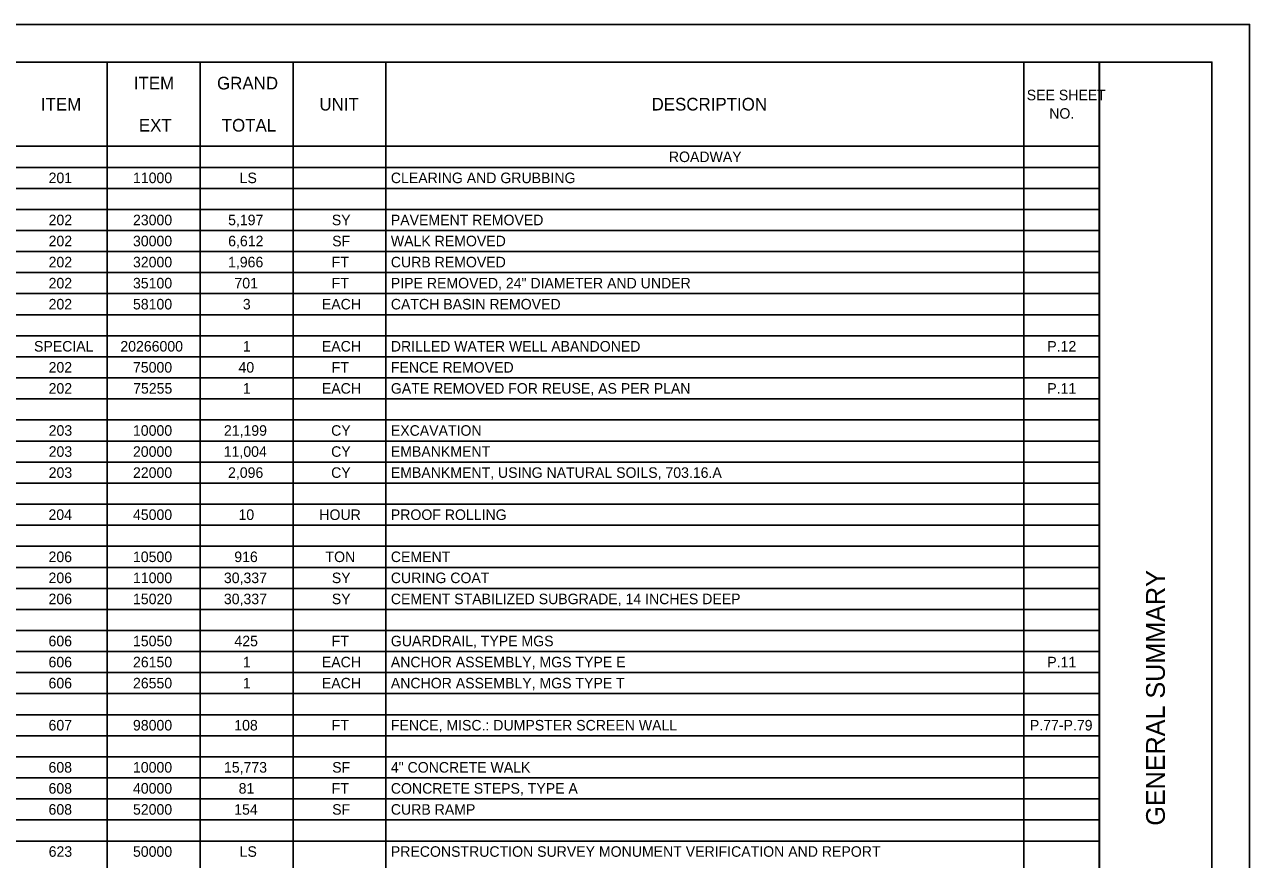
# Model space of a CAD drawing. Extents: x 0 to 34, y 0 to 22.
# Drawn here: x 17.71 to 34, y 10.89 to 22 of the extents above; entities that cross this region are included whole.
import ezdxf

# ---------------------------------------------------------------- set-up
doc = ezdxf.new("R2010")
doc.units = 0
for name, color, linetype in [('SH_Border', 7, 'Continuous'), ('SH_Cut_Line', 7, 'Continuous'), ('SH_Data', 7, 'Continuous'), ('SH_Text', 7, 'Continuous')]:
    doc.layers.add(name, color=color, linetype=linetype)

msp = doc.modelspace()

# ---------------------------------------------------------------- linework, layer by layer
at = {"layer": 'SH_Border'}
msp.add_line((32, 0.5), (32, 21.5), dxfattribs=at)
msp.add_lwpolyline([(1.5, 21.5), (33.5, 21.5), (33.5, 0.5), (1.5, 0.5)], close=True, dxfattribs=at)
at = {"layer": 'SH_Cut_Line'}
msp.add_lwpolyline([(0, 0), (34, 0), (34, 22), (0, 22)], close=True, dxfattribs=at)
at = {"layer": 'SH_Text'}
for p, q in [((1.5, 21.5), (32.004, 21.5)), ((18.811, 21.5), (18.811, 0.5)), ((20.046, 21.5), (20.046, 0.5)), ((21.281, 21.5), (21.281, 0.5)), ((22.516, 21.5), (22.516, 0.5)), ((30.999, 21.5), (30.999, 0.5)), ((32.004, 21.5), (32.004, 0.5)), ((1.5, 20.38), (32.004, 20.38)), ((1.5, 20.1), (32.004, 20.1)), ((1.5, 19.82), (32.004, 19.82)), ((1.5, 19.54), (32.004, 19.54)), ((1.5, 19.26), (32.004, 19.26)), ((1.5, 18.98), (32.004, 18.98)), ((1.5, 18.7), (32.004, 18.7)), ((1.5, 18.42), (32.004, 18.42)), ((1.5, 18.14), (32.004, 18.14)), ((1.5, 17.86), (32.004, 17.86)), ((1.5, 17.58), (32.004, 17.58)), ((1.5, 17.3), (32.004, 17.3)), ((1.5, 17.02), (32.004, 17.02)), ((1.5, 16.74), (32.004, 16.74)), ((1.5, 16.46), (32.004, 16.46)), ((1.5, 16.18), (32.004, 16.18)), ((1.5, 15.9), (32.004, 15.9)), ((1.5, 15.62), (32.004, 15.62)), ((1.5, 15.34), (32.004, 15.34)), ((1.5, 15.06), (32.004, 15.06)), ((1.5, 14.78), (32.004, 14.78)), ((1.5, 14.5), (32.004, 14.5)), ((1.5, 14.22), (32.004, 14.22)), ((1.5, 13.94), (32.004, 13.94)), ((1.5, 13.66), (32.004, 13.66)), ((1.5, 13.38), (32.004, 13.38)), ((1.5, 13.1), (32.004, 13.1)), ((1.5, 12.82), (32.004, 12.82)), ((1.5, 12.54), (32.004, 12.54)), ((1.5, 12.26), (32.004, 12.26)), ((1.5, 11.98), (32.004, 11.98)), ((1.5, 11.7), (32.004, 11.7)), ((1.5, 11.42), (32.004, 11.42)), ((1.5, 11.14), (32.004, 11.14))]:
    msp.add_line(p, q, dxfattribs=at)

# ---------------------------------------------------------------- texts
at = {"layer": 'SH_Data'}
msp.add_text('GENERAL SUMMARY', height=0.25, rotation=90, dxfattribs=at).set_placement((32.875, 11.344))
at = {"layer": 'SH_Text'}
for s, height, p in [('ITEM', 0.168, (19.164, 21.136)), ('GRAND', 0.168, (20.271, 21.136)), ('ITEM', 0.168, (17.928, 20.856)), ('UNIT', 0.168, (21.632, 20.856)), ('DESCRIPTION', 0.168, (26.049, 20.856)), ('SEE SHEET ', 0.14, (31.038, 20.992)), ('NO.', 0.14, (31.337, 20.747)), ('EXT', 0.168, (19.231, 20.576)), ('TOTAL', 0.168, (20.333, 20.576)), ('ROADWAY', 0.14, (26.279, 20.17)), ('201', 0.14, (18.031, 19.89)), ('11000', 0.14, (19.153, 19.89)), ('LS', 0.14, (20.571, 19.89)), ('CLEARING AND GRUBBING', 0.14, (22.582, 19.89)), ('202', 0.14, (18.031, 19.33)), ('23000', 0.14, (19.153, 19.33)), ('5,197', 0.14, (20.418, 19.33)), ('SY', 0.14, (21.797, 19.33)), ('PAVEMENT REMOVED', 0.14, (22.582, 19.33)), ('202', 0.14, (18.031, 19.05)), ('30000', 0.14, (19.153, 19.05)), ('6,612', 0.14, (20.419, 19.05)), ('SF', 0.14, (21.802, 19.05)), ('WALK REMOVED', 0.14, (22.582, 19.05)), ('202', 0.14, (18.031, 18.77)), ('32000', 0.14, (19.153, 18.77)), ('1,966', 0.14, (20.417, 18.77)), ('FT', 0.14, (21.795, 18.77)), ('CURB REMOVED', 0.14, (22.582, 18.77)), ('202', 0.14, (18.031, 18.49)), ('35100', 0.14, (19.153, 18.49)), ('701', 0.14, (20.502, 18.49)), ('FT', 0.14, (21.795, 18.49)), ('PIPE REMOVED, 24" DIAMETER AND UNDER', 0.14, (22.582, 18.49)), ('202', 0.14, (18.031, 18.21)), ('58100', 0.14, (19.153, 18.21)), ('3', 0.14, (20.614, 18.21)), ('EACH', 0.14, (21.665, 18.21)), ('CATCH BASIN REMOVED', 0.14, (22.582, 18.21)), ('SPECIAL', 0.14, (17.837, 17.65)), ('20266000', 0.14, (18.985, 17.65)), ('1', 0.14, (20.614, 17.65)), ('EACH', 0.14, (21.665, 17.65)), ('DRILLED WATER WELL ABANDONED', 0.14, (22.582, 17.65)), ('P.12', 0.14, (31.311, 17.65)), ('202', 0.14, (18.031, 17.37)), ('75000', 0.14, (19.153, 17.37)), ('40', 0.14, (20.556, 17.37)), ('FT', 0.14, (21.795, 17.37)), ('FENCE REMOVED', 0.14, (22.582, 17.37)), ('202', 0.14, (18.031, 17.09)), ('75255', 0.14, (19.155, 17.09)), ('1', 0.14, (20.614, 17.09)), ('EACH', 0.14, (21.665, 17.09)), ('GATE REMOVED FOR REUSE, AS PER PLAN', 0.14, (22.582, 17.09)), ('P.11', 0.14, (31.311, 17.09)), ('203', 0.14, (18.032, 16.53)), ('10000', 0.14, (19.153, 16.53)), ('21,199', 0.14, (20.362, 16.53)), ('CY', 0.14, (21.788, 16.53)), ('EXCAVATION', 0.14, (22.582, 16.53)), ('203', 0.14, (18.032, 16.25)), ('20000', 0.14, (19.153, 16.25)), ('11,004', 0.14, (20.36, 16.25)), ('CY', 0.14, (21.788, 16.25)), ('EMBANKMENT', 0.14, (22.582, 16.25)), ('203', 0.14, (18.032, 15.97)), ('22000', 0.14, (19.153, 15.97)), ('2,096', 0.14, (20.417, 15.97)), ('CY', 0.14, (21.788, 15.97)), ('EMBANKMENT, USING NATURAL SOILS, 703.16.A', 0.14, (22.582, 15.97)), ('204', 0.14, (18.029, 15.41)), ('45000', 0.14, (19.153, 15.41)), ('10', 0.14, (20.556, 15.41)), ('HOUR', 0.14, (21.631, 15.41)), ('PROOF ROLLING', 0.14, (22.582, 15.41)), ('206', 0.14, (18.03, 14.85)), ('10500', 0.14, (19.153, 14.85)), ('916', 0.14, (20.5, 14.85)), ('TON', 0.14, (21.713, 14.85)), ('CEMENT', 0.14, (22.582, 14.85)), ('206', 0.14, (18.03, 14.57)), ('11000', 0.14, (19.153, 14.57)), ('30,337', 0.14, (20.362, 14.57)), ('SY', 0.14, (21.797, 14.57)), ('CURING COAT', 0.14, (22.582, 14.57)), ('206', 0.14, (18.03, 14.29)), ('15020', 0.14, (19.153, 14.29)), ('30,337', 0.14, (20.362, 14.29)), ('SY', 0.14, (21.797, 14.29)), ('CEMENT STABILIZED SUBGRADE, 14 INCHES DEEP', 0.14, (22.582, 14.29)), ('606', 0.14, (18.03, 13.73)), ('15050', 0.14, (19.153, 13.73)), ('425', 0.14, (20.502, 13.73)), ('FT', 0.14, (21.795, 13.73)), ('GUARDRAIL, TYPE MGS', 0.14, (22.582, 13.73)), ('606', 0.14, (18.03, 13.45)), ('26150', 0.14, (19.153, 13.45)), ('1', 0.14, (20.614, 13.45)), ('EACH', 0.14, (21.665, 13.45)), ('ANCHOR ASSEMBLY, MGS TYPE E', 0.14, (22.582, 13.45)), ('P.11', 0.14, (31.311, 13.45)), ('606', 0.14, (18.03, 13.17)), ('26550', 0.14, (19.153, 13.17)), ('1', 0.14, (20.614, 13.17)), ('EACH', 0.14, (21.665, 13.17)), ('ANCHOR ASSEMBLY, MGS TYPE T', 0.14, (22.582, 13.17)), ('607', 0.14, (18.03, 12.61)), ('98000', 0.14, (19.153, 12.61)), ('108', 0.14, (20.5, 12.61)), ('FT', 0.14, (21.795, 12.61)), ('FENCE, MISC.: DUMPSTER SCREEN WALL', 0.14, (22.582, 12.61)), ('P.77-P.79', 0.14, (31.08, 12.61)), ('608', 0.14, (18.03, 12.05)), ('10000', 0.14, (19.153, 12.05)), ('15,773', 0.14, (20.363, 12.05)), ('SF', 0.14, (21.802, 12.05)), ('4" CONCRETE WALK', 0.14, (22.582, 12.05)), ('608', 0.14, (18.03, 11.77)), ('40000', 0.14, (19.153, 11.77)), ('81', 0.14, (20.558, 11.77)), ('FT', 0.14, (21.795, 11.77)), ('CONCRETE STEPS, TYPE A', 0.14, (22.582, 11.77)), ('608', 0.14, (18.03, 11.49)), ('52000', 0.14, (19.153, 11.49)), ('154', 0.14, (20.499, 11.49)), ('SF', 0.14, (21.802, 11.49)), ('CURB RAMP', 0.14, (22.582, 11.49)), ('623', 0.14, (18.032, 10.93)), ('50000', 0.14, (19.153, 10.93)), ('LS', 0.14, (20.571, 10.93)), ('PRECONSTRUCTION SURVEY MONUMENT VERIFICATION AND REPORT', 0.14, (22.582, 10.93))]:
    msp.add_text(s, height=height, dxfattribs=at).set_placement(p)

doc.saveas('drawing.dxf')
